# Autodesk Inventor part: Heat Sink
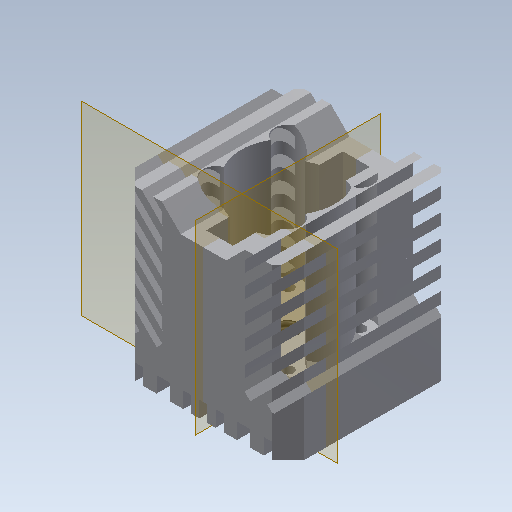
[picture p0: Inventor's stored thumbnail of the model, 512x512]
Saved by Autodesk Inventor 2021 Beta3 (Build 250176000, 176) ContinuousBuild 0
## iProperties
Created: 2012-08
Part Number: Heat Sink
Material: Aluminum 6061
Document SubType Name: Modeling
Designer: John
Density: 2.71 g/cm^3
Mass: 80.2934 g
Surface Area: 233.008 cm^2
Volume: 29.6286 cm^3
Appearance: Aluminum - Flat
Author: John
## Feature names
1. Extrusion1
2. Extrusion2
3. Extrusion3
4. Extrusion4
5. Extrusion5
6. Hole1
7. Hole2
8. Chamfer1
9. Extrusion6
10. Extrusion8
11. Extrusion9
12. Extrusion11
13. Mirror1
14. Extrusion12
15. Extrusion13
16. Sweep1
17. Extrusion14
## Parameters: d0 = 40.005 mm, d1 = 40.005 mm, d2 = 40.005 mm, d3 = 0, d4 = 3.81 mm, d5 = 5.715 mm, d6 = 8.89 mm, d7 = 12.065 mm, d8 = 15.24 mm, d9 = 17.145 mm, d10 = 19.05 mm, d11 = 3.81 mm, d12 = 0, d13 = 3.81 mm, d14 = 3.81 mm, d15 = 3.81 mm, d16 = 0, d17 = 13.97 mm, d18 = 21.336 mm, d19 = 0.762 mm, d20 = 0, d21 = 0.508 mm, d22 = 0, d23 = 25.4 mm, d24 = 25.4 mm, d25 = 4.9784 mm, d26 = 19.05 mm, d27 = 9.525 mm, d28 = 6.35 mm, d29 = 82 deg, d30 = 25.4 mm, d31 = 118 deg, d32 = 16.9672 mm, d33 = 2.667 mm, d34 = 19.05 mm, d35 = 9.525 mm, d36 = 6.35 mm, d37 = 82 deg, d38 = 25.4 mm, d39 = 118 deg, d40 = 3.81 mm, d41 = 3.175 mm, d42 = 45 deg, d43 = 10.795 mm, d44 = 4.445 mm, d45 = 0, d54 = 45 deg, d55 = 31.115 mm, d56 = 0, d57 = 6.35 mm, d58 = 3.81 mm, d59 = 16.51 mm, d60 = 0, d61 = 45 deg, d64 = 1.905 mm, d65 = 3.81 mm, d66 = 1.905 mm, d67 = 3.81 mm, d73 = 1.905 mm, d74 = 1.905 mm, d75 = 1.905 mm, d76 = 1.905 mm, d77 = 1.905 mm, d78 = 1.905 mm, d79 = 1.905 mm, d80 = 1.905 mm, d81 = 1.905 mm, d82 = 1.905 mm, d83 = 1.905 mm, d84 = 30.48 mm, d85 = 16.51 mm, d86 = 0, d87 = 10.27442 mm, d88 = 22.225 mm, d89 = 6.35 mm, d90 = 23.495 mm, d91 = 11.7475 mm, d92 = 31.115 mm, d93 = 0, d94 = 11.1125 mm, d95 = 31.115 mm, d96 = 0, d97 = 2.54 mm, d99 = 2.54 mm, d100 = 3.175 mm, d101 = 0, d104 = 0, d105 = 2.1336 mm, d106 = 0.8636 mm, d107 = 1.016 mm, d108 = 0.3175 mm, d109 = 0, d110 = 0
